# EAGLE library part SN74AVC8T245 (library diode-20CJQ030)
Ti's SN74AVC8T245 8-bit dual supply bus transceiver with configurable voltage transsaltion and 3-state outputs Description: This 8-bit noninverting bus transceiver uses two separate configurable power-supply rails. The SN74AVC8T245 is optimized to operate with VCCA/VCCB set at 1.4 V to 3.6 V. It is operational with VCCA/VCCB as low as 1.2 V. The A port is designed to track VCCA. VCCA accepts any supply voltage from 1.2 V to 3.6 V. The B port is designed to track VCCB. VCCB accepts any supply voltage from 1.2 V to 3.6 V. This allows for universal low-voltage bidirectional translation between any of the 1.2-V, 1.5-V, 1.8-V, 2.5-V, and 3.3-V voltage nodes. The SN74AVC8T245 is designed for asynchronous communication between data buses. The device transmits data from the A bus to the B bus or from the B bus to the A bus, depending on the logic level at the direction-control (DIR) input. The output-enable (OE) input can be used to disable the outputs so the buses are effectively isolated. The SN74AVC8T245 is designed so the control pins (DIR and OE) are supplied by VCCA. The SN74AVC8T245 solution is compatible with a single-supply system and can be replaced later with a '245 function, with minimal printed circuit board redesign. This device is fully specified for partial-power-down applications using Ioff. The Ioff circuitry disables the outputs, preventing damaging current backflow through the device when it is powered down. The VCC isolation feature ensures that if either VCC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
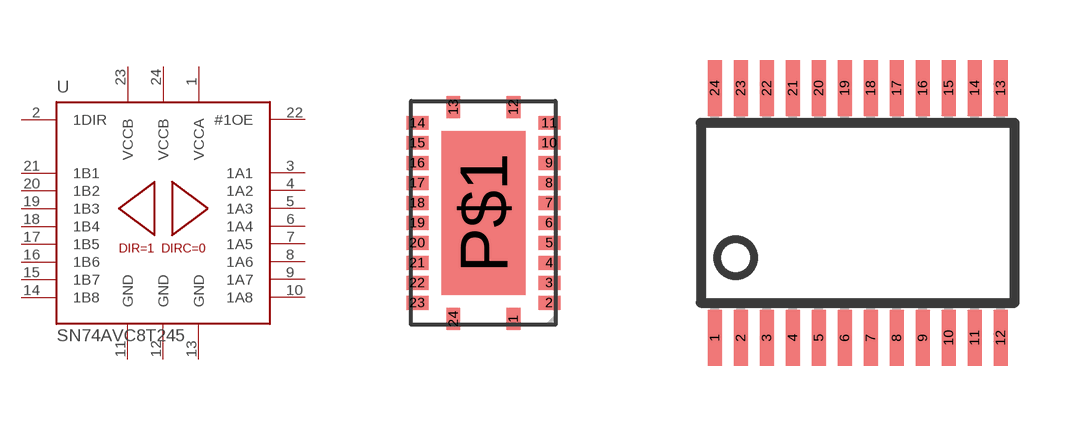
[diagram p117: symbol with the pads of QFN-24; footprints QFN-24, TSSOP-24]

Designator prefix U

## SN74AVC8T245-RHL  [QFN-24]
1  VCCA  pwr
2  1DIR  in
3  1A1
4  1A2
5  1A3
6  1A4
7  1A5
8  1A6
9  1A7
10  1A8
11  GND  pwr
12  GND  pwr
13  GND  pwr
14  1B8
15  1B7
16  1B6
17  1B5
18  1B4
19  1B3
20  1B2
21  1B1
22  #1OE  in
23  VCCB  pwr
24  VCCB  pwr

## SN74AVC8T245-PW  [TSSOP-24]
Pads as for QFN-24

## Footprint QFN-24 (pad centres in mm)
smd 0.35 x 0.55: 1 0.75,-2.65; 12 0.75,2.65; 13 -0.75,2.65; 24 -0.75,-2.65
smd 0.55 x 0.35: 2 1.65,-2.25; 3 1.65,-1.75; 4 1.65,-1.25; 5 1.65,-0.75; 6 1.65,-0.25; 7 1.65,0.25; 8 1.65,0.75; 9 1.65,1.25; 10 1.65,1.75; 11 1.65,2.25; 14 -1.65,2.25; 15 -1.65,1.75; 16 -1.65,1.25; 17 -1.65,0.75; 18 -1.65,0.25; 19 -1.65,-0.25; 20 -1.65,-0.75; 21 -1.65,-1.25; 22 -1.65,-1.75; 23 -1.65,-2.25
smd 2.1 x 4.1: P$1 0,0

## Footprint TSSOP-24 (pad centres in mm)
TSSOP-24 4.5mm body ie. bq24702/3
smd 0.35 x 1.4: 1 -3.725,-3.125; 2 -3.075,-3.125; 3 -2.425,-3.125; 4 -1.775,-3.125; 5 -1.125,-3.125; 6 -0.475,-3.125; 7 0.175,-3.125; 8 0.825,-3.125; 9 1.475,-3.125; 10 2.125,-3.125; 11 2.775,-3.125; 12 3.425,-3.125; 13 3.425,3.125; 14 2.775,3.125; 15 2.125,3.125; 16 1.475,3.125; 17 0.825,3.125; 18 0.175,3.125; 19 -0.475,3.125; 20 -1.125,3.125; 21 -1.775,3.125; 22 -2.425,3.125; 23 -3.075,3.125; 24 -3.725,3.125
